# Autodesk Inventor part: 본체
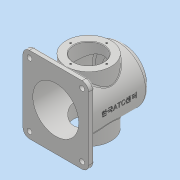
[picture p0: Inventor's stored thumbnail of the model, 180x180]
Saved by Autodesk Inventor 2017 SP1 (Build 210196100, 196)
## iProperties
Part Number: 본체
Material: 일반
Document SubType Name: Modeling
Designer: MRC
Density: 1 g/cm^3
Appearance: 기본값
Mass: 774.551 g
Surface Area: 1031.78 cm^2
Volume: 774.551 cm^3
Author: MRC
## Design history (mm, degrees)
sketch "스케치1"
  geometry: C1 r 50 at (0, 0); 1 further point
  constraints: 1 centre point, 1 coincident
  dimensions: "d0" = 100 diameter of C1
extrude "돌출1" new body sketch "스케치1" stored distance "d1" = 120; taper "d2" = 0 deg
node "작업 평면1"
sketch "스케치2"
  geometry: C1 r 41 at (0, 0); 1 further point
  constraints: 1 centre point, 1 coincident
  dimensions: "d4" = 82 diameter of C1
extrude "돌출2" join sketch "스케치2" stored distance "d5" = 100; taper "d6" = 0 deg
sketch "스케치3"
  geometry: C1 r 41 at (0, 0) reference; C2 r 27 at (0, 0)
  constraints: 1 centre point, 1 coincident
  dimensions: "d7" = 54 diameter of C2
extrude "돌출3" cut sketch "스케치3" distance "d8" = 59; taper "d9" = 0 deg
sketch "스케치4"
  geometry: C1 r 27 at (0, 0) reference; 1 further point
  constraints: 1 vertical alignment
  dimensions: "d10" = 33 distance of point (0, 33) C1.centre
hole "구멍1" sketch "스케치4" at (0, 33) diameter "d11" = 3.242; stored, may be unused: countersink angle "d15" = 90 deg, drill point angle "d17" = 118 deg; dims "d12" = 8, "d13" = 4, "d14" = 2, "d16" = 10
sketch "스케치5"
  geometry: L1 (60, 70)-(-60, 70); L2 (-60, 70)-(-60, -70); L3 (-60, -70)-(60, -70); L4 (60, -70)-(60, 70); L5 (60, 70)-(-60, -70); L6 (-60, 70)-(60, -70); C1 r 50 at (0, 0) reference
  constraints: 12 end point, 2 midpoint, 2 parallel, 1 horizontal, 1 perpendicular
  dimensions: "d21" = 120 distance of L3.end L2.end; "d22" = 140 distance of L2.end L1.end
extrude "돌출4" join sketch "스케치5" distance "d23" = 10; taper "d24" = 0 deg
sketch "스케치7"
  geometry: C1 r 50 at (0, 0) reference; C2 r 41 at (0, 0)
  constraints: 1 centre point, 1 coincident
  dimensions: "d28" = 82 diameter of C2
extrude "돌출6" join sketch "스케치7" distance "d29" = 5; taper "d30" = 0 deg
sketch "스케치8"
  geometry: C1 r 41 at (0, 0) reference; C2 r 27 at (0, 0)
  constraints: 1 centre point, 1 coincident
  dimensions: "d31" = 54 diameter of C2
extrude "돌출7" cut sketch "스케치8" distance "d32" = 50; taper "d33" = 0 deg
sketch "스케치9"
  geometry: C1 r 27 at (0, 0) reference; 1 further point
  constraints: 1 horizontal alignment
  dimensions: "d34" = 33 distance of C1.centre point (-33, 0)
hole "구멍2" sketch "스케치9" at (-33, 0) diameter "d35" = 3.242; stored, may be unused: countersink angle "d39" = 90 deg, drill point angle "d41" = 118 deg; dims "d36" = 8, "d37" = 4, "d38" = 2, "d40" = 10
node "작업 평면2"
sketch "스케치10"
  geometry: L1 (-50, 70)-(-50, -70) reference; L2 (-60, -70)-(-60, 70) reference; 2 further points
  constraints: 1 horizontal alignment, 1 other
  dimensions: "d64" = 66 distance from line of L2 point (6, 0)
feature "엠보싱1" sketch "스케치10" dims "d47" = 0.5, "d48" = 0
fillet "모깎기1" dims "d49" = 12
sketch "스케치11"
  geometry: C1 r 4.5 at (-48, -58); C2 r 4.5 at (48, -58); C3 r 4.5 at (48, 58); C4 r 4.5 at (-48, 58); A1 r 12 centre (-48, 58) between (-48, 70) and (-60, 58) reference; A2 r 12 centre (-48, -58) between (-60, -58) and (-48, -70) reference; A3 r 12 centre (48, -58) between (48, -70) and (60, -58) reference; A4 r 12 centre (48, 58) between (60, 58) and (48, 70) reference
  constraints: 4 centre point, 4 coincident
  dimensions: "d50" = 9 diameter of C1; "d51" = 9 diameter of C2; "d52" = 9 diameter of C3; "d53" = 9 diameter of C4
extrude "돌출8" cut sketch "스케치11" distance "d54" = 50; taper "d55" = 0 deg
chamfer "모따기1" distance "d56" = 1; stored, may be unused: second distance "d57" = 2, angle "d58" = 45 deg
fillet "모깎기2" dims "d59" = 6, "d60" = 3
node "솔리드1"
pattern_circular "원형 패턴1" dims angle "d19" = 360 deg
mirror "미러1"
sketch "스케치12"
  geometry: C1 r 42 at (0, 0); 1 further point
  constraints: 1 centre point, 1 coincident
  dimensions: "d61" = 84 diameter of C1
extrude "돌출5" cut sketch "스케치12" distance "d62" = 112; taper "d63" = 0 deg
pattern_circular "원형 패턴2" dims angle "d43" = 360 deg
other parameters: "d3" = 59, "d45" = 52.5
